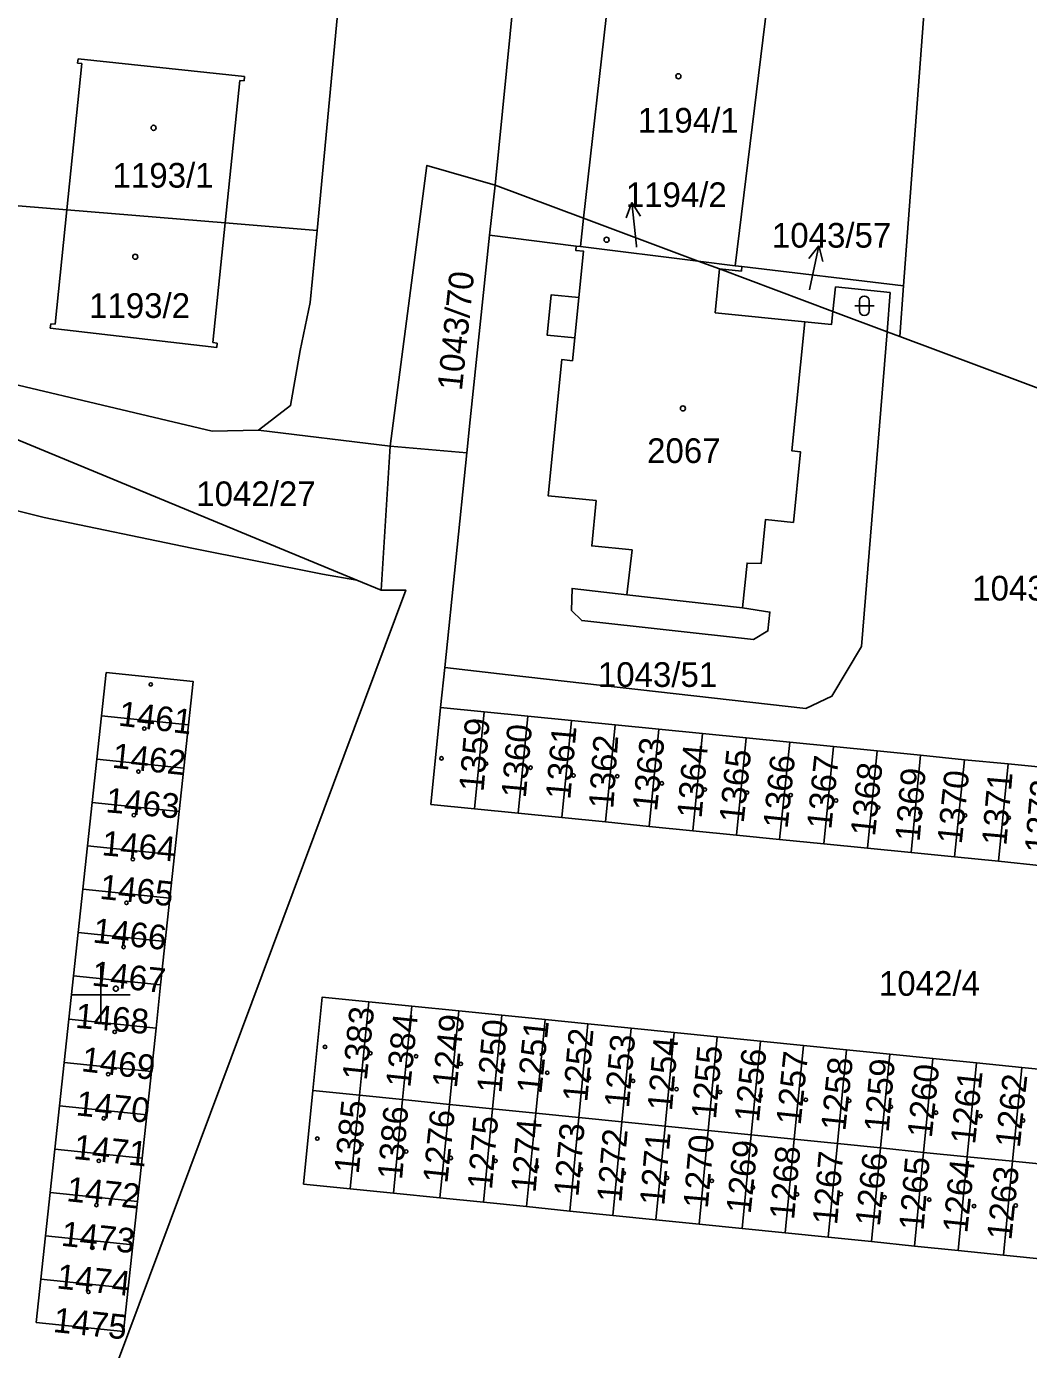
# Model space of a CAD drawing. Extents: x -779302 to -774398, y -1144902 to -1142831.
# Drawn here: x -775205.1 to -775136.1, y -1144424.4 to -1144333.3 of the extents above; entities that cross this region are included whole.
import ezdxf

# ---------------------------------------------------------------- set-up
doc = ezdxf.new("R2010")
doc.units = 0
for name, color, linetype in [('hektosit - Vrstva 5', 7, 'Continuous'), ('Hranice parcel', 7, 'Continuous'), ('Parcelní čísla', 7, 'Continuous'), ('Pop  PČ popisy', 7, 'Continuous'), ('Vnitřní kresba', 7, 'Continuous'), ('Značky budov', 7, 'Continuous'), ('Značky kultur', 7, 'Continuous')]:
    doc.layers.add(name, color=color, linetype=linetype)

msp = doc.modelspace()

# ---------------------------------------------------------------- linework, layer by layer
at = {"layer": 'hektosit - Vrstva 5'}
for p, q in [((-775200, -1144398), (-775200, -1144402)), ((-775202, -1144400), (-775198, -1144400))]:
    msp.add_line(p, q, dxfattribs=at)
at = {"layer": 'Hranice parcel'}
for p, q in [((-775172.87, -1144344.25), (-775170.93, -1144324.96)), ((-775183.24, -1144327.44), (-775185.12, -1144347.36)), ((-775144.74, -1144351.18), (-775142.99, -1144327.77)), ((-775172.87, -1144344.25), (-775173.24, -1144347.7)), ((-775173.24, -1144347.7), (-775167.28, -1144348.44)), ((-775144.74, -1144351.18), (-775145, -1144354.68)), ((-775182.38, -1144371.44), (-775227.51, -1144352.79)), ((-775145.88, -1144354.35), (-775149.61, -1144352.95)), ((-775145, -1144354.68), (-775145.88, -1144354.35)), ((-775145, -1144354.68), (-775120.83, -1144363.72)), ((-775189.15, -1144361.13), (-775180.09, -1144362.23)), ((-775180.09, -1144362.23), (-775180.7, -1144372.14)), ((-775174.82, -1144362.68), (-775180.09, -1144362.23)), ((-775174.82, -1144362.68), (-775176.33, -1144377.47)), ((-775180.7, -1144372.14), (-775182.38, -1144371.44)), ((-775176.33, -1144377.47), (-775176.62, -1144380.22)), ((-775173.62, -1144380.52), (-775176.62, -1144380.22)), ((-775199.97, -1144380.8), (-775200.29, -1144383.78)), ((-775199.97, -1144380.8), (-775193.97, -1144381.42)), ((-775174.28, -1144387.19), (-775173.62, -1144380.52)), ((-775170.61, -1144380.82), (-775173.62, -1144380.52)), ((-775171.27, -1144387.49), (-775170.61, -1144380.82)), ((-775167.6, -1144381.12), (-775170.61, -1144380.82)), ((-775168.27, -1144387.79), (-775167.6, -1144381.12)), ((-775164.6, -1144381.41), (-775167.6, -1144381.12)), ((-775194.29, -1144384.4), (-775193.97, -1144381.42)), ((-775165.26, -1144388.09), (-775164.6, -1144381.41)), ((-775161.59, -1144381.71), (-775164.6, -1144381.41)), ((-775162.26, -1144388.4), (-775161.59, -1144381.71)), ((-775158.59, -1144382.01), (-775161.59, -1144381.71)), ((-775159.25, -1144388.7), (-775158.59, -1144382.01)), ((-775155.58, -1144382.31), (-775158.59, -1144382.01)), ((-775156.25, -1144389), (-775155.58, -1144382.31)), ((-775152.58, -1144382.61), (-775155.58, -1144382.31)), ((-775153.29, -1144389.3), (-775152.58, -1144382.61)), ((-775149.57, -1144382.91), (-775152.58, -1144382.61)), ((-775150.24, -1144389.6), (-775149.57, -1144382.91)), ((-775146.57, -1144383.21), (-775149.57, -1144382.91)), ((-775200.29, -1144383.78), (-775200.61, -1144386.76)), ((-775200.29, -1144383.78), (-775194.29, -1144384.4)), ((-775147.23, -1144389.91), (-775146.57, -1144383.21)), ((-775143.57, -1144383.51), (-775146.57, -1144383.21)), ((-775144.23, -1144390.21), (-775143.57, -1144383.51)), ((-775140.56, -1144383.81), (-775143.57, -1144383.51)), ((-775141.23, -1144390.51), (-775140.56, -1144383.81)), ((-775137.55, -1144384.1), (-775140.56, -1144383.81)), ((-775194.61, -1144387.38), (-775194.29, -1144384.4)), ((-775138.22, -1144390.81), (-775137.55, -1144384.1)), ((-775134.55, -1144384.4), (-775137.55, -1144384.1)), ((-775200.61, -1144386.76), (-775200.93, -1144389.75)), ((-775200.61, -1144386.76), (-775194.61, -1144387.38)), ((-775194.93, -1144390.37), (-775194.61, -1144387.38)), ((-775174.28, -1144387.19), (-775171.27, -1144387.49)), ((-775171.27, -1144387.49), (-775168.27, -1144387.79)), ((-775168.27, -1144387.79), (-775165.26, -1144388.09)), ((-775165.26, -1144388.09), (-775162.26, -1144388.4)), ((-775162.26, -1144388.4), (-775159.25, -1144388.7)), ((-775159.25, -1144388.7), (-775156.25, -1144389)), ((-775156.25, -1144389), (-775153.29, -1144389.3)), ((-775153.29, -1144389.3), (-775150.24, -1144389.6)), ((-775200.93, -1144389.75), (-775201.25, -1144392.73)), ((-775200.93, -1144389.75), (-775194.93, -1144390.37)), ((-775195.25, -1144393.35), (-775194.93, -1144390.37)), ((-775150.24, -1144389.6), (-775147.23, -1144389.91)), ((-775147.23, -1144389.91), (-775144.23, -1144390.21)), ((-775144.23, -1144390.21), (-775141.23, -1144390.51)), ((-775141.23, -1144390.51), (-775138.22, -1144390.81)), ((-775138.22, -1144390.81), (-775135.21, -1144391.11)), ((-775201.25, -1144392.73), (-775201.57, -1144395.71)), ((-775201.25, -1144392.73), (-775195.25, -1144393.35)), ((-775195.57, -1144396.33), (-775195.25, -1144393.35)), ((-775201.57, -1144395.71), (-775201.89, -1144398.7)), ((-775201.57, -1144395.71), (-775195.57, -1144396.33)), ((-775195.89, -1144399.32), (-775195.57, -1144396.33)), ((-775201.89, -1144398.7), (-775202.21, -1144401.68)), ((-775201.89, -1144398.7), (-775195.89, -1144399.32)), ((-775196.21, -1144402.3), (-775195.89, -1144399.32)), ((-775182.2, -1144406.92), (-775181.56, -1144400.48)), ((-775178.59, -1144400.78), (-775181.56, -1144400.48)), ((-775178.59, -1144400.78), (-775179.23, -1144407.22)), ((-775175.36, -1144401.11), (-775178.59, -1144400.78)), ((-775176.01, -1144407.55), (-775175.36, -1144401.11)), ((-775172.4, -1144401.41), (-775175.36, -1144401.11)), ((-775202.21, -1144401.68), (-775202.53, -1144404.66)), ((-775202.21, -1144401.68), (-775196.21, -1144402.3)), ((-775173.04, -1144407.85), (-775172.4, -1144401.41)), ((-775169.43, -1144401.7), (-775172.4, -1144401.41)), ((-775170.07, -1144408.15), (-775169.43, -1144401.7)), ((-775166.47, -1144402), (-775169.43, -1144401.7)), ((-775167.1, -1144408.45), (-775166.47, -1144402)), ((-775163.5, -1144402.3), (-775166.47, -1144402)), ((-775196.53, -1144405.28), (-775196.21, -1144402.3)), ((-775164.13, -1144408.75), (-775163.5, -1144402.3)), ((-775160.53, -1144402.6), (-775163.5, -1144402.3)), ((-775161.16, -1144409.05), (-775160.53, -1144402.6)), ((-775157.57, -1144402.9), (-775160.53, -1144402.6)), ((-775158.2, -1144409.35), (-775157.57, -1144402.9)), ((-775154.6, -1144403.2), (-775157.57, -1144402.9)), ((-775155.23, -1144409.65), (-775154.6, -1144403.2)), ((-775151.64, -1144403.5), (-775154.6, -1144403.2)), ((-775152.27, -1144409.95), (-775151.64, -1144403.5)), ((-775148.67, -1144403.79), (-775151.64, -1144403.5)), ((-775149.3, -1144410.25), (-775148.67, -1144403.79)), ((-775145.7, -1144404.09), (-775148.67, -1144403.79)), ((-775202.53, -1144404.66), (-775202.85, -1144407.65)), ((-775202.53, -1144404.66), (-775196.53, -1144405.28)), ((-775146.33, -1144410.55), (-775145.7, -1144404.09)), ((-775142.74, -1144404.39), (-775145.7, -1144404.09)), ((-775143.37, -1144410.85), (-775142.74, -1144404.39)), ((-775139.73, -1144404.69), (-775142.74, -1144404.39)), ((-775140.36, -1144411.15), (-775139.73, -1144404.69)), ((-775136.61, -1144405.01), (-775139.73, -1144404.69)), ((-775196.85, -1144408.27), (-775196.53, -1144405.28)), ((-775137.24, -1144411.46), (-775136.61, -1144405.01)), ((-775133.63, -1144405.31), (-775136.61, -1144405.01)), ((-775185.41, -1144406.6), (-775182.2, -1144406.92)), ((-775202.85, -1144407.65), (-775203.17, -1144410.63)), ((-775202.85, -1144407.65), (-775196.85, -1144408.27)), ((-775182.84, -1144413.37), (-775182.2, -1144406.92)), ((-775182.2, -1144406.92), (-775179.23, -1144407.22)), ((-775179.23, -1144407.22), (-775179.87, -1144413.67)), ((-775179.23, -1144407.22), (-775176.01, -1144407.55)), ((-775176.01, -1144407.55), (-775176.66, -1144413.99)), ((-775176.01, -1144407.55), (-775173.04, -1144407.85)), ((-775197.17, -1144411.25), (-775196.85, -1144408.27)), ((-775173.04, -1144407.85), (-775173.67, -1144414.29)), ((-775173.04, -1144407.85), (-775170.07, -1144408.15)), ((-775170.07, -1144408.15), (-775170.7, -1144414.59)), ((-775170.07, -1144408.15), (-775167.1, -1144408.45)), ((-775167.1, -1144408.45), (-775167.73, -1144414.9)), ((-775167.1, -1144408.45), (-775164.13, -1144408.75)), ((-775164.13, -1144408.75), (-775164.75, -1144415.2)), ((-775164.13, -1144408.75), (-775161.16, -1144409.05)), ((-775161.16, -1144409.05), (-775161.79, -1144415.5)), ((-775161.16, -1144409.05), (-775158.2, -1144409.35)), ((-775158.2, -1144409.35), (-775158.82, -1144415.8)), ((-775158.2, -1144409.35), (-775155.23, -1144409.65)), ((-775155.23, -1144409.65), (-775155.86, -1144416.1)), ((-775155.23, -1144409.65), (-775152.27, -1144409.95)), ((-775152.27, -1144409.95), (-775152.89, -1144416.4)), ((-775152.27, -1144409.95), (-775149.3, -1144410.25)), ((-775149.3, -1144410.25), (-775149.93, -1144416.7)), ((-775149.3, -1144410.25), (-775146.33, -1144410.55)), ((-775203.17, -1144410.63), (-775203.49, -1144413.61)), ((-775203.17, -1144410.63), (-775197.17, -1144411.25)), ((-775197.49, -1144414.23), (-775197.17, -1144411.25)), ((-775146.33, -1144410.55), (-775146.95, -1144417)), ((-775146.33, -1144410.55), (-775143.37, -1144410.85)), ((-775143.37, -1144410.85), (-775144, -1144417.3)), ((-775143.37, -1144410.85), (-775140.36, -1144411.15)), ((-775140.36, -1144411.15), (-775140.99, -1144417.6)), ((-775140.36, -1144411.15), (-775137.24, -1144411.46)), ((-775137.87, -1144417.92), (-775137.24, -1144411.46)), ((-775134.27, -1144411.76), (-775137.24, -1144411.46)), ((-775203.49, -1144413.61), (-775203.81, -1144416.6)), ((-775203.49, -1144413.61), (-775197.49, -1144414.23)), ((-775182.84, -1144413.37), (-775179.87, -1144413.67)), ((-775179.87, -1144413.67), (-775176.66, -1144413.99)), ((-775176.66, -1144413.99), (-775173.67, -1144414.29)), ((-775197.81, -1144417.22), (-775197.49, -1144414.23)), ((-775173.67, -1144414.29), (-775170.7, -1144414.59)), ((-775170.7, -1144414.59), (-775167.73, -1144414.9)), ((-775167.73, -1144414.9), (-775164.75, -1144415.2)), ((-775164.75, -1144415.2), (-775161.79, -1144415.5)), ((-775161.79, -1144415.5), (-775158.82, -1144415.8)), ((-775158.82, -1144415.8), (-775155.86, -1144416.1)), ((-775203.81, -1144416.6), (-775204.13, -1144419.58)), ((-775203.81, -1144416.6), (-775197.81, -1144417.22)), ((-775155.86, -1144416.1), (-775152.89, -1144416.4)), ((-775152.89, -1144416.4), (-775149.93, -1144416.7)), ((-775149.93, -1144416.7), (-775146.95, -1144417)), ((-775198.13, -1144420.2), (-775197.81, -1144417.22)), ((-775146.95, -1144417), (-775144, -1144417.3)), ((-775144, -1144417.3), (-775140.99, -1144417.6)), ((-775140.99, -1144417.6), (-775137.87, -1144417.92)), ((-775137.87, -1144417.92), (-775134.91, -1144418.22)), ((-775204.13, -1144419.58), (-775198.13, -1144420.2))]:
    msp.add_line(p, q, dxfattribs=at)
for points in [[(-775180.09, -1144362.23), (-775177.56, -1144342.89), (-775172.87, -1144344.25)], [(-775172.87, -1144344.25), (-775166.77, -1144346.53), (-775158.88, -1144349.49)], [(-775212.14, -1144345.14), (-775202.35, -1144345.94), (-775191.45, -1144346.84), (-775185.12, -1144347.36)], [(-775185.12, -1144347.36), (-775185.59, -1144352.33), (-775186.28, -1144355.64), (-775186.94, -1144359.43), (-775189.15, -1144361.13)], [(-775173.24, -1144347.7), (-775174.59, -1144360.4), (-775174.82, -1144362.68)], [(-775149.61, -1144352.95), (-775149.7, -1144353.84), (-775151.54, -1144353.66), (-775152.43, -1144362.55), (-775151.85, -1144362.61), (-775152.33, -1144367.47), (-775154.25, -1144367.28), (-775154.55, -1144370.31), (-775155.52, -1144370.27), (-775155.83, -1144373.35), (-775153.95, -1144373.65), (-775154.08, -1144374.94), (-775155.07, -1144375.53), (-775166.9, -1144374.23), (-775167.61, -1144373.53), (-775167.57, -1144372.02), (-775163.79, -1144372.45), (-775163.43, -1144369.36), (-775166.21, -1144369.09), (-775165.91, -1144365.97), (-775169.22, -1144365.64), (-775168.28, -1144356.26), (-775167.54, -1144356.34), (-775167.38, -1144354.77), (-775169.27, -1144354.58), (-775169, -1144351.79), (-775167.1, -1144351.98), (-775166.78, -1144348.79), (-775167.31, -1144348.74), (-775167.28, -1144348.44)], [(-775167.28, -1144348.44), (-775166.99, -1144348.48), (-775158.88, -1144349.49)], [(-775158.88, -1144349.49), (-775156.33, -1144349.8), (-775155.88, -1144349.86), (-775144.74, -1144351.18)], [(-775149.61, -1144352.95), (-775157.41, -1144350.01), (-775158.88, -1144349.49)], [(-775145.88, -1144354.35), (-775147.65, -1144376.02), (-775149.68, -1144379.44), (-775151.47, -1144380.29), (-775171.96, -1144377.97), (-775176.33, -1144377.47)], [(-775189.15, -1144361.13), (-775192.34, -1144361.18), (-775213.28, -1144356.23)], [(-775241.44, -1144360.01), (-775230.77, -1144362.69), (-775229.2, -1144363.12), (-775220.08, -1144365.37), (-775209.29, -1144367.97), (-775208.86, -1144365.9), (-775203.92, -1144367.13), (-775193.75, -1144369.24), (-775184.75, -1144371.03), (-775182.38, -1144371.44)], [(-775199.5, -1144427.02), (-775179.02, -1144372.13), (-775180.7, -1144372.14)], [(-775193.97, -1144381.42), (-775193.65, -1144378.43), (-775199.64, -1144377.81), (-775199.97, -1144380.8)], [(-775176.62, -1144380.22), (-775177.28, -1144386.89), (-775174.28, -1144387.19)], [(-775181.56, -1144400.48), (-775184.77, -1144400.16), (-775185.41, -1144406.6)], [(-775185.41, -1144406.6), (-775186.05, -1144413.04), (-775182.84, -1144413.37)], [(-775204.13, -1144419.58), (-775204.45, -1144422.56), (-775198.45, -1144423.18), (-775198.13, -1144420.2)]]:
    msp.add_lwpolyline(points, dxfattribs=at)
at = {"layer": 'Pop  PČ popisy'}
for p, q in [((-775163.454, -1144345.445), (-775163.847, -1144346.494)), ((-775163.14, -1144348.43), (-775163.454, -1144345.445)), ((-775163.454, -1144345.445), (-775162.851, -1144346.389)), ((-775163.13, -1144348.51), (-775163.14, -1144348.43)), ((-775150.576, -1144348.415), (-775151.274, -1144349.29)), ((-775151.2, -1144351.35), (-775150.576, -1144348.415)), ((-775150.576, -1144348.415), (-775150.294, -1144349.498)), ((-775151.22, -1144351.46), (-775151.2, -1144351.35))]:
    msp.add_line(p, q, dxfattribs=at)
at = {"layer": 'Vnitřní kresba'}
for p, q in [((-775164.99, -1144330.62), (-775166.77, -1144346.53)), ((-775154.13, -1144331.83), (-775156.33, -1144349.8)), ((-775201.61, -1144335.84), (-775201.58, -1144335.54)), ((-775190.11, -1144336.77), (-775201.58, -1144335.54)), ((-775202.35, -1144345.94), (-775201.31, -1144335.87)), ((-775201.31, -1144335.87), (-775201.61, -1144335.84)), ((-775191.45, -1144346.84), (-775190.44, -1144337.04)), ((-775190.14, -1144337.07), (-775190.44, -1144337.04)), ((-775190.11, -1144336.77), (-775190.14, -1144337.07)), ((-775203.16, -1144353.83), (-775202.35, -1144345.94)), ((-775166.99, -1144348.48), (-775166.77, -1144346.53)), ((-775192.3, -1144355.09), (-775191.45, -1144346.84)), ((-775157.41, -1144350.01), (-775157.71, -1144353.04)), ((-775155.91, -1144350.16), (-775157.41, -1144350.01)), ((-775155.88, -1144349.86), (-775155.91, -1144350.16)), ((-775167.1, -1144351.98), (-775167.38, -1144354.77)), ((-775149.44, -1144351.26), (-775149.61, -1144352.95)), ((-775145.66, -1144351.63), (-775149.44, -1144351.26)), ((-775145.88, -1144354.35), (-775145.66, -1144351.63)), ((-775157.71, -1144353.04), (-775151.54, -1144353.66)), ((-775203.49, -1144354.09), (-775203.46, -1144353.79)), ((-775203.46, -1144353.79), (-775203.16, -1144353.83)), ((-775192.03, -1144355.42), (-775203.49, -1144354.09)), ((-775192.3, -1144355.09), (-775192, -1144355.12)), ((-775192, -1144355.12), (-775192.03, -1144355.42)), ((-775163.79, -1144372.45), (-775155.83, -1144373.35))]:
    msp.add_line(p, q, dxfattribs=at)
at = {"layer": 'Značky budov'}
for centre, radius in [((-775160.247, -1144336.749), 0.175), ((-775196.377, -1144340.299), 0.175), ((-775165.187, -1144348.009), 0.175), ((-775197.637, -1144349.179), 0.175), ((-775159.937, -1144359.619), 0.175), ((-775196.575, -1144378.629), 0.117), ((-775197.015, -1144381.669), 0.117), ((-775176.555, -1144383.719), 0.117), ((-775173.485, -1144384.089), 0.117), ((-775197.425, -1144384.629), 0.117), ((-775170.425, -1144384.359), 0.117), ((-775167.465, -1144384.899), 0.117), ((-775164.455, -1144384.949), 0.117), ((-775161.385, -1144385.439), 0.117), ((-775158.425, -1144385.869), 0.117), ((-775155.525, -1144386.079), 0.117), ((-775152.515, -1144386.249), 0.117), ((-775149.395, -1144386.619), 0.117), ((-775197.735, -1144387.629), 0.117), ((-775146.485, -1144387.109), 0.117), ((-775143.585, -1144387.479), 0.117), ((-775140.515, -1144387.649), 0.117), ((-775137.505, -1144387.809), 0.117), ((-775197.805, -1144390.669), 0.117), ((-775198.245, -1144393.669), 0.117), ((-775198.445, -1144396.709), 0.117), ((-775198.977, -1144399.579), 0.175), ((-775199.055, -1144402.559), 0.117), ((-775184.575, -1144403.589), 0.117), ((-775181.455, -1144404.029), 0.117), ((-775178.305, -1144404.229), 0.117), ((-775175.225, -1144404.759), 0.117), ((-775172.315, -1144404.799), 0.117), ((-775199.505, -1144405.469), 0.117), ((-775169.275, -1144405.369), 0.117), ((-775166.405, -1144405.729), 0.117), ((-775163.365, -1144405.929), 0.117), ((-775160.375, -1144406.499), 0.117), ((-775157.375, -1144406.699), 0.117), ((-775154.585, -1144406.949), 0.117), ((-775151.475, -1144407.229), 0.117), ((-775148.485, -1144407.299), 0.117), ((-775145.615, -1144407.709), 0.117), ((-775199.805, -1144408.509), 0.117), ((-775142.505, -1144408.119), 0.117), ((-775139.455, -1144408.349), 0.117), ((-775136.515, -1144408.659), 0.117), ((-775185.105, -1144409.899), 0.117), ((-775182.065, -1144410.309), 0.117), ((-775200.145, -1144411.439), 0.117), ((-775178.985, -1144410.789), 0.117), ((-775175.915, -1144411.239), 0.117), ((-775172.835, -1144411.439), 0.117), ((-775170.005, -1144411.839), 0.117), ((-775166.975, -1144412.009), 0.117), ((-775164.015, -1144412.289), 0.117), ((-775161.025, -1144412.609), 0.117), ((-775157.945, -1144412.819), 0.117), ((-775155.115, -1144413.259), 0.117), ((-775152.075, -1144413.749), 0.117), ((-775149.065, -1144413.729), 0.117), ((-775146.055, -1144413.939), 0.117), ((-775142.975, -1144414.109), 0.117), ((-775200.315, -1144414.479), 0.117), ((-775139.895, -1144414.549), 0.117), ((-775137.025, -1144414.509), 0.117), ((-775200.595, -1144417.419), 0.117), ((-775200.865, -1144420.459), 0.117)]:
    msp.add_circle(centre, radius, dxfattribs=at)
at = {"layer": 'Značky kultur'}
for p, q in [((-775148.111, -1144352.551), (-775146.769, -1144352.551)), ((-775147.775, -1144352.215), (-775147.775, -1144352.886)), ((-775147.105, -1144352.886), (-775147.105, -1144352.215))]:
    msp.add_line(p, q, dxfattribs=at)
for centre, start, end in [((-775147.44, -1144352.216), 0, 180), ((-775147.44, -1144352.886), 180, 359.98789)]:
    msp.add_arc(centre, 0.335, start, end, dxfattribs=at)

# ---------------------------------------------------------------- texts
at = {"layer": 'Parcelní čísla'}
for s, p in [('1194/1', (-775163.05, -1144340.63)), ('1193/1', (-775199.2, -1144344.42)), ('1194/2', (-775163.87, -1144345.76)), ('1043/57', (-775153.808, -1144348.55)), ('1193/2', (-775200.82, -1144353.39)), ('2067', (-775162.4, -1144363.38)), ('1042/27', (-775193.44, -1144366.35)), ('1043/50', (-775140.02, -1144372.85)), ('1043/51', (-775165.79, -1144378.8)), ('1042/4', (-775146.44, -1144400.07))]:
    msp.add_text(s, height=1.7, dxfattribs=at).set_placement(p)
for s, rotation, p in [('1043/70', 84, (-775175.154, -1144358.448)), ('1461', 353, (-775198.853, -1144381.453)), ('1359', 85, (-775173.663, -1144386.054)), ('1360', 85, (-775170.753, -1144386.484)), ('1361', 85, (-775167.693, -1144386.594)), ('1362', 86, (-775164.732, -1144387.219)), ('1462', 354, (-775199.278, -1144384.355)), ('1363', 84, (-775161.724, -1144387.408)), ('1364', 85, (-775158.653, -1144387.884)), ('1365', 84, (-775155.754, -1144388.218)), ('1366', 84, (-775152.734, -1144388.598)), ('1367', 84, (-775149.724, -1144388.648)), ('1368', 84, (-775146.714, -1144389.128)), ('1369', 85, (-775143.643, -1144389.494)), ('1370', 84, (-775140.744, -1144389.668)), ('1371', 85, (-775137.673, -1144389.764)), ('1463', 355, (-775199.714, -1144387.426)), ('1372', 85, (-775134.723, -1144390.304)), ('1464', 355, (-775199.984, -1144390.386)), ('1465', 354, (-775200.138, -1144393.385)), ('1466', 354, (-775200.608, -1144396.395)), ('1467', 354, (-775200.678, -1144399.355)), ('1468', 355, (-775201.811, -1144402.268)), ('1383', 84, (-775181.704, -1144405.938)), ('1384', 84, (-775178.704, -1144406.428)), ('1249', 84, (-775175.504, -1144406.468)), ('1250', 85, (-775172.433, -1144406.814)), ('1251', 84, (-775169.684, -1144406.868)), ('1252', 85, (-775166.523, -1144407.424)), ('1253', 85, (-775163.653, -1144407.834)), ('1254', 85, (-775160.693, -1144408.034)), ('1469', 353, (-775201.403, -1144405.253)), ('1255', 85, (-775157.663, -1144408.604)), ('1256', 84, (-775154.704, -1144408.818)), ('1257', 84, (-775151.834, -1144409.018)), ('1258', 84, (-775148.754, -1144409.418)), ('1259', 85, (-775145.773, -1144409.514)), ('1260', 84, (-775142.804, -1144409.898)), ('1261', 84, (-775139.824, -1144410.338)), ('1262', 84, (-775136.744, -1144410.578)), ('1470', 354, (-775201.768, -1144408.295)), ('1385', 84, (-775182.264, -1144412.378)), ('1386', 85, (-775179.273, -1144412.774)), ('1276', 84, (-775176.154, -1144413.028)), ('1275', 85, (-775173.083, -1144413.454)), ('1274', 85, (-775170.083, -1144413.664)), ('1273', 85, (-775167.133, -1144413.944)), ('1272', 85, (-775164.173, -1144414.344)), ('1471', 354, (-775201.938, -1144411.295)), ('1271', 85, (-775161.223, -1144414.554)), ('1270', 85, (-775158.223, -1144414.754)), ('1269', 84, (-775155.274, -1144415.128)), ('1268', 85, (-775152.283, -1144415.524)), ('1267', 85, (-775149.323, -1144415.884)), ('1266', 84, (-775146.384, -1144415.988)), ('1265', 85, (-775143.373, -1144416.274)), ('1264', 84, (-775140.364, -1144416.458)), ('1263', 84, (-775137.324, -1144416.938)), ('1472', 354, (-775202.418, -1144414.205)), ('1473', 354, (-775202.788, -1144417.275)), ('1474', 354, (-775203.098, -1144420.215)), ('1475', 354, (-775203.338, -1144423.215))]:
    msp.add_text(s, height=1.7, rotation=rotation, dxfattribs=at).set_placement(p)

doc.saveas('drawing.dxf')
